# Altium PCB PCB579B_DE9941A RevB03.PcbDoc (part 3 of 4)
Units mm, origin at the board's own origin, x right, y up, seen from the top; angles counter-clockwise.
Board outline 85.8 x 54.18 mm, 6 copper layers (Top, L2C, L3C, L4C, L5C, Bottom), stack 1.627 mm thick; 536 components, 371 nets, 1413 pads, 798 vias.
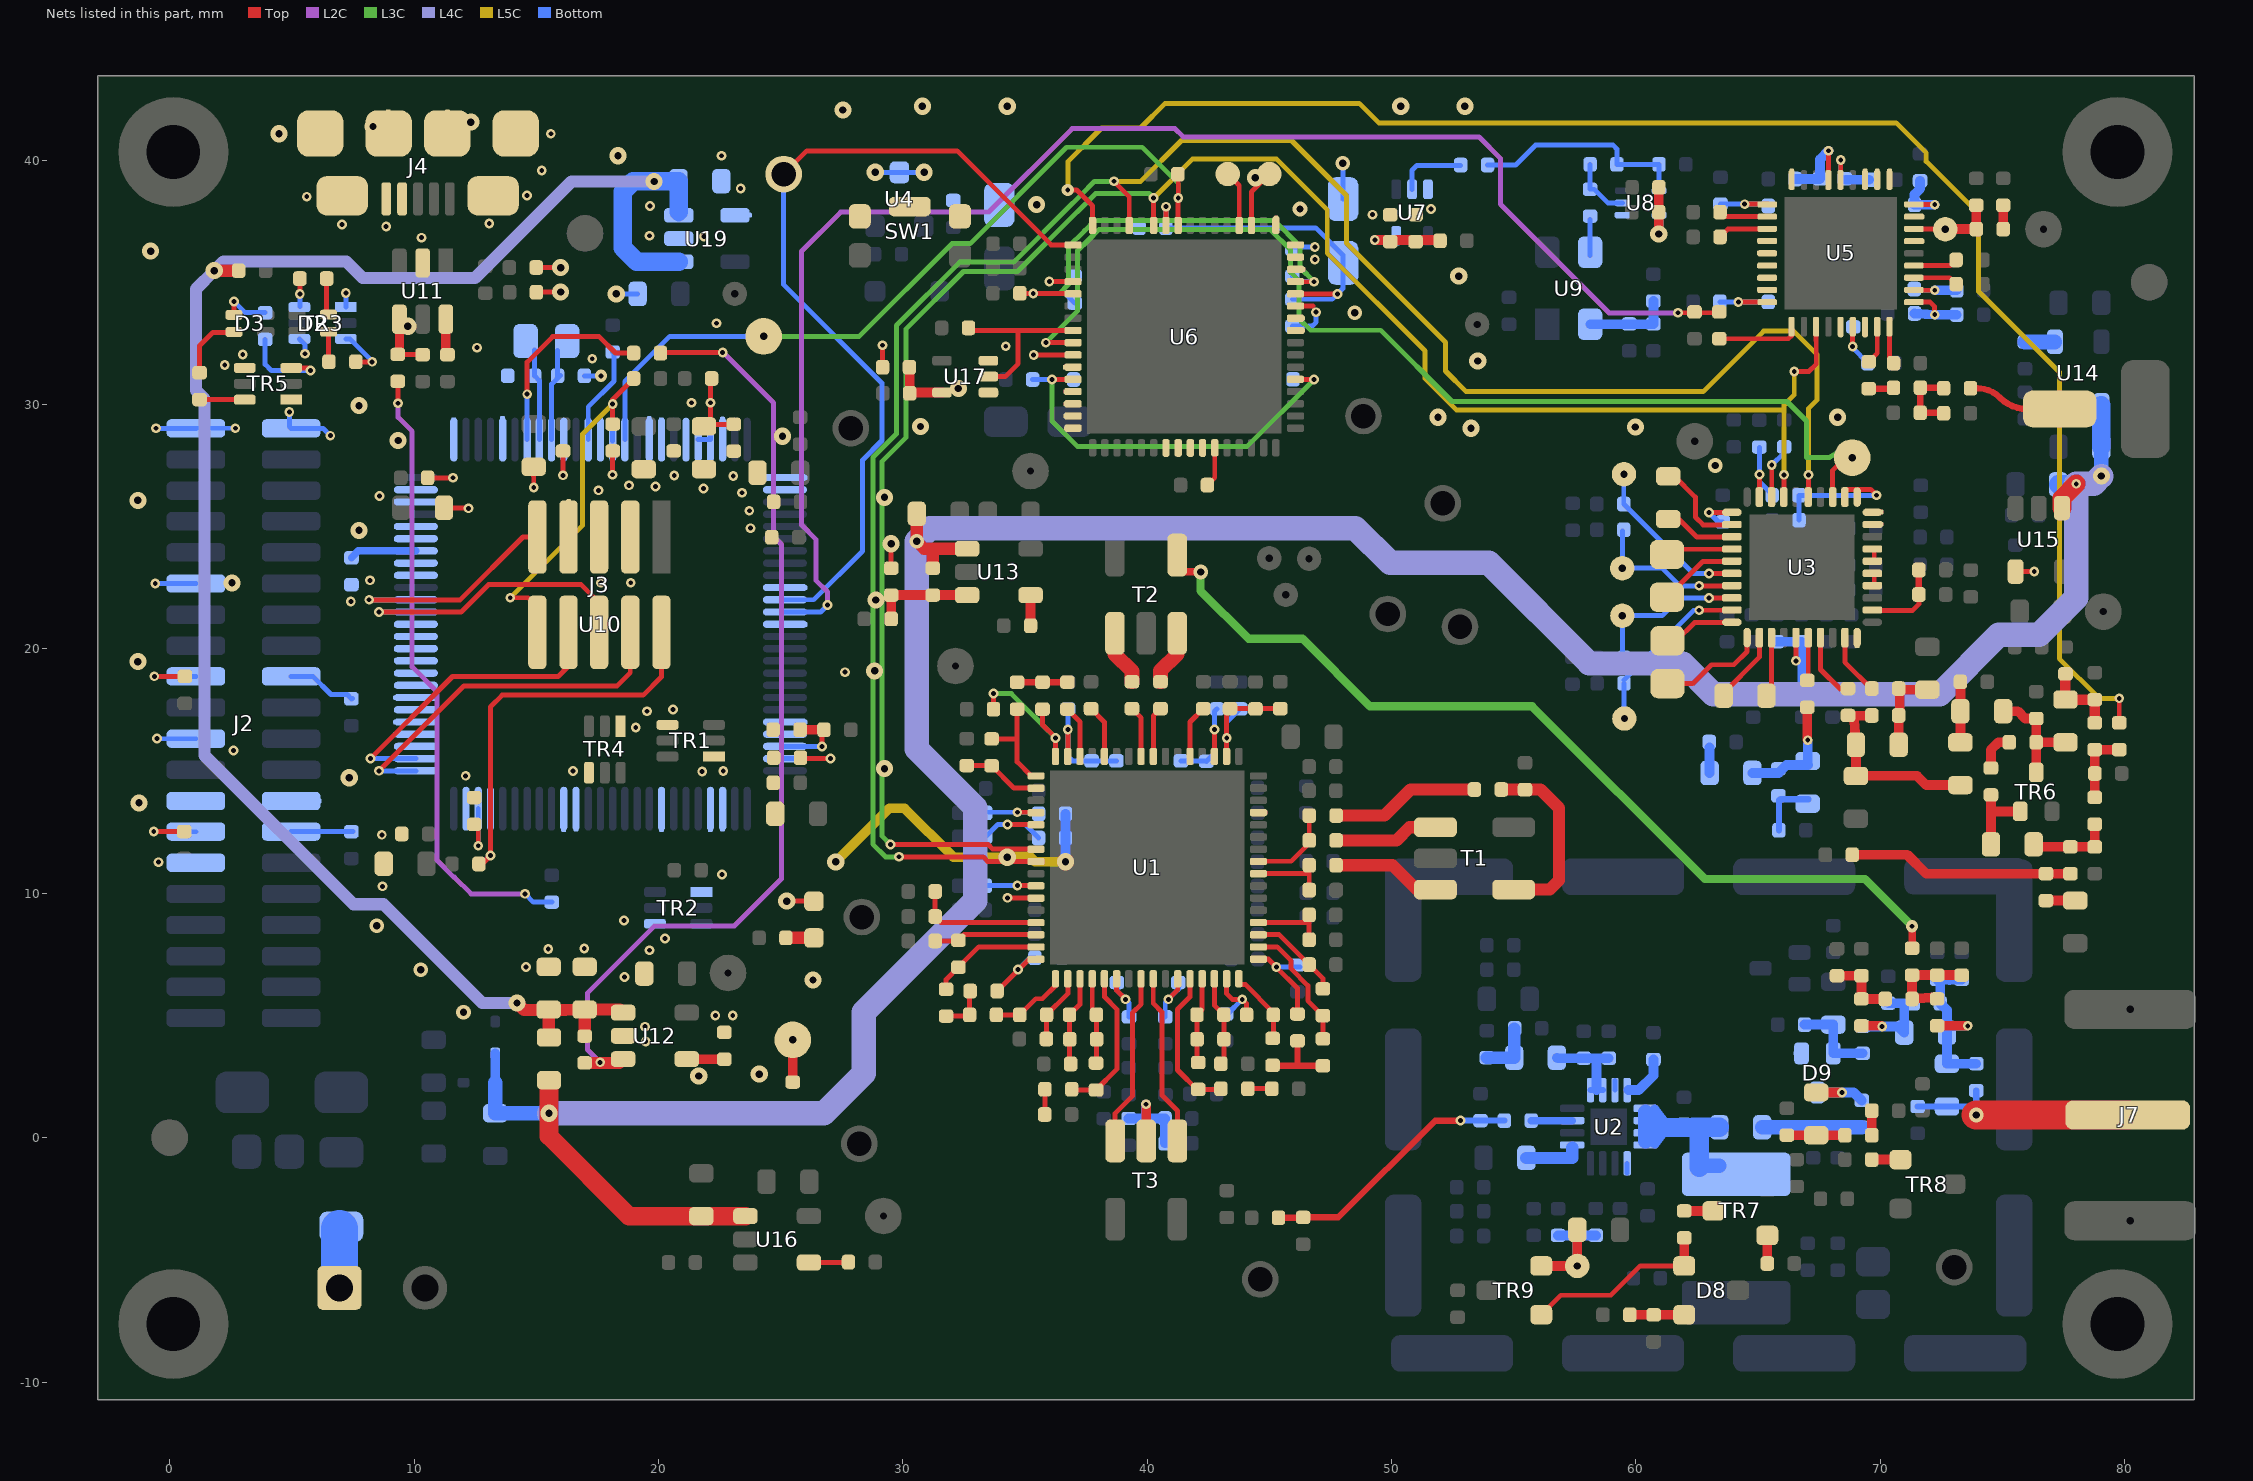
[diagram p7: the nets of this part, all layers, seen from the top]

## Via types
v1: diameter 0.4, hole 0.2, Top to Bottom, tented both sides, 372 vias
v2: diameter 0.7, hole 0.3, Top to Bottom, tented both sides, 177 vias
v3: diameter 0.7, hole 0.3, L5C to Bottom, tented both sides, 52 vias
v4: diameter 0.5, hole 0.2, Top to Bottom, tented both sides, 35 vias
v5: diameter 0.7, hole 0.3, Top to L2C, tented both sides, 33 vias
v6: diameter 0.6, hole 0.2, Top to Bottom, tented bottom, 30 vias
v7: diameter 0.6, hole 0.3, Top to L2C, tented bottom, 28 vias
v8: diameter 0.6, hole 0.3, Top to L2C, 24 vias
v9: diameter 0.6, hole 0.3, Top to Bottom, tented both sides, 22 vias
v10: diameter 0.6, hole 0.3, Top to Bottom, tented bottom, 9 vias
v11: diameter 0.5, hole 0.2, Top to Bottom, tented top, 6 vias
v12: diameter 0.45, hole 0.2, Top to Bottom, 5 vias
v13: diameter 0.6, hole 0.3, Top to Bottom, 3 vias
v14: diameter 0.406, hole 0.2, Top to Bottom, tented both sides, 2 vias

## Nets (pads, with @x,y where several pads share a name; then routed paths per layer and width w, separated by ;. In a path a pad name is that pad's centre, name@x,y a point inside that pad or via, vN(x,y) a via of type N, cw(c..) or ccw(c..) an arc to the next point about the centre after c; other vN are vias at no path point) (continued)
GNDD: C1.2 C2.2 C3.2 C4.2 C5.2 C6.2 C10.2 C12.2 C13.2 C19.1 C20.1 C21.1 C22.1 C23.1 C24.1 C25.1 C26.1 C27.1 C28.1 C29.1 C30.1 C31.1 C32.1 C33.1 C34.1 C35.2 C46.1 C47.1 C81.2 C82.2 C83.2 C84.2 C139.1 C144.1 C160.1 C192.2 C193.1 C194.1 C195.2 C196.2 C197.2 C198.1 C199.2 D4.2 J2.1 J2.2 J2.12 J2.22 J2.30 J3.3 J3.5 J4.5 J4.6 J4.7 J4.8 J4.11 R14.1 R20.1 R82.2 SW1.1 SW1.3 SW1.5 TP11.1 TR1.1 TR1.4 TR2.1 TR2.4 TR3.1 TR3.4 TR4.1 TR4.4 TR5.1 TR5.4 U1.59 U3.21 U3.22 U4.3 U6.4 U6.10 U6.43 U6.47 U6.48 U7.3 U10.10 U10.20 U10.27 U10.74 U10.99 U11.2 U12.2 U17.3 U19.2 | length 52.9
  Top w0.2: v1(34.288,9.812) U1.59@35.452,9.807
  Top w0.203: C193.1@10.554,26.997 v1@11.597,26.997 ; C194.1@11.229,25.772 v1@12.203,25.772 ; C29.1@14.896,27.448 v1(14.9,26.6) ; C34.1@15.002,35.605 15.007,35.6 v2(16,35.6) ; C35.2@15.01,34.589 15.021,34.6 v2(16,34.6) ; C24.1@16.096,28.098 16.096,27.104 v1(16.1,27.1) ; v1(18.125,27.125) 18.129,27.129 C25.1@18.129,28.097 ; v2(25.25,9.675) D4.2@26.363,9.674 ; C160.1@29.175,31.529 v1(29.175,32.425) ; C199.2@29.525,23.3 v5(29.525,24.3) ; v1(35.354,32.024) 35.358,32.028 U6.10@36.967,32.028 ; v1(35.996,35.028) U6.4@36.967,35.028 ; U6.43@46.067,34.028 46.787,34.028 ; U3.22@68.55,26.213 U3.22@68.55,26.525 ; U3.22@68.55,26.525 69.6,26.525 v1(69.848,26.284) ; U3.21@69.05,26.213 U3.21@69.05,26.525
  Top w0.4: R82.2@25.5,2.275 TP11.1@25.5,4
  L5C w0.4: v2(27.255,11.285) 29.445,13.475 30.075,13.475 32.075,11.475 v3(34.275,11.475) 34.3,11.5 35.201,11.5 35.413,11.288 v3(36.658,11.288)
  Bottom w0.2: C198.1@16.974,31.171 v4(17.652,31.171)
  Bottom w0.203: v1@-0.582,22.672 J2.12@1.076,22.672 ; v1@-0.556,29.022 J2.2@1.076,29.022 1.081,29.027 v1(2.69,29.027) ; v1@-0.505,16.322 J2.22@1.076,16.322 ; v1(4.9,29.688) 4.9,29.098 J2.1@4.976,29.022 6.276,29.022 v1(6.576,28.722) ; TR3.4@5.311,32.68 5.545,32.447 v1(5.545,32.075) ; TR3.1@7.211,33.98 v1(7.211,34.564) ; v2(18.275,34.525) C197.2@19.15,34.525 ; v2@28.878,39.497 U4.3@29.864,39.497 v2@30.872,39.497 ; C2.2@45.942,33.203 46.744,33.203 46.911,33.371 v1(46.911,33.777) ; C6.2@46.033,36.444 v1(46.861,36.444) ; v9(48.004,39.873) 48.004,38.425 C1.2@48.014,38.397 ; C139.1@66.673,25.268 C144.1@66.673,26.284 v1(69.848,26.284)
  Bottom w0.4: v3(36.658,11.288) C46.1@36.658,12.26 C47.1@36.658,13.251
  other v1: 19.479,3.932 19.454,4.542 22.33,4.995 23.041,4.995 18.616,6.574 14.577,6.98 19.632,7.666 15.492,7.717 16.965,7.742 20.267,8.148 18.59,8.885 8.71,10.282 22.604,10.765 -0.46,11.273 8.684,12.39 12.113,14.803 21.791,14.981 16.508,15.006 22.654,15.006 2.614,15.845 -0.51,16.327 19.073,16.784 19.53,17.445 20.597,17.521 27.633,19.045 7.414,21.941 -0.587,22.677 17.651,22.703 18.87,22.703 8.202,22.804 23.772,24.938 23.721,25.649 12.225,25.75 8.583,26.259 23.416,26.386 17.549,26.487 21.842,26.563 19.886,26.64 18.794,26.69 11.6,27 23.061,27.071 20.648,27.097 -0.561,29.027 21.359,30.069 2.258,31.618 17.295,31.872 2.995,32.05 12.575,32.325 34.211,32.38 22.375,33.325 46.861,35.936 10.31,36.825 21.867,36.876 19.632,36.901 8.862,37.282 7.059,37.358 13.079,37.409 49.223,37.765 51.61,37.993 19.657,38.12 5.611,38.501 14.628,38.552 23.366,38.832 15.225,39.575 22.578,40.178 15.6,41.075
  other v2: 24.125,2.6 26.325,6.45 -1.25,13.7 7.35,14.725 -1.3,19.475 -1.3,26.075 51.9,29.475 7.75,29.95 53.525,31.775 52.75,35.25 -0.775,36.275 28.875,39.5 30.875,39.5 18.35,40.175 4.475,41.075 27.55,42.05 30.8,42.2 34.275,42.2 50.375,42.2 53,42.2
  other v3: 21.65,2.525 29.25,15.1 28.85,19.1 28.9,22 2.55,22.7 7.75,24.85 29.25,26.2 9.35,28.525 25.075,28.7 53.25,29.025 59.975,29.075 30.725,29.1 68.25,29.475 32.275,30.65 9.75,33.2 35.475,38.175 44.425,39.275 8.325,41.375 12.325,41.55
  other v9: 12.025,5.125 10.275,6.875 8.475,8.675 63.25,27.5 48.5,33.75 46.25,38
GPIOA/LNA: R102.1 U6.64 | length 67.3
  Top w0.203: v4(36.751,38.781) 37.107,38.781 37.767,38.121 U6.64@37.767,37.328 ; R102.1@79.775,16.975 v1(79.775,17.975)
  L5C w0.203: v4(36.751,38.781) 36.751,39.937 38.13,41.315 39.724,41.315 40.733,42.324 48.676,42.324 49.475,41.525 70.65,41.525 71.875,40.3 71.875,39.95 74.025,37.8 74.025,34.625 77.325,31.325 77.325,19.6 78.95,17.975 v1(79.775,17.975)
GPIOB/SLOT: TL10.1 U6.1 U10.36 | length 35.2
  Top w0.2: TL10.1@25.125,39.425 26.075,40.375 32.225,40.375 36.072,36.528 U6.1@36.967,36.528
  Bottom w0.2: TL10.1@25.125,39.425 25.125,34.9 29.15,30.875 29.15,28.525 28.35,27.725 28.35,24 26.358,22.008 U10.36@25.179,22.008
GPIOC/TXD: R122.1 U6.8 U17.2 | length 7.1
  Top w0.203: R122.1@32.792,33.028 U6.8@37.067,33.028 ; U17.2@33.503,31.14 34.19,31.14 34.719,31.669 34.719,33.028
GPIOD/RXD: TP17.1 U3.23 U6.9 | length 45.7
  Top w0.203: v1@35.853,32.533 U6.9@37.062,32.533 ; U3.23@68.05,26.275 68.05,27.301 TP17.1@68.67,27.921
  L3C w0.203: v1(35.853,32.528) 37.158,33.833 37.158,36.292 37.597,36.731 37.601,36.731 38.021,37.151 45.038,37.151 45.87,36.319 45.87,35.404 46.206,35.068 46.206,33.519 46.689,33.036 49.557,33.036 52.474,30.119 66.181,30.119 66.975,29.325 66.975,27.836 67.111,27.825 67.9,27.825 68.211,28.011 68.806,28.011 TP17.1@68.857,27.96
IASIG: C54.1 U1.46 | length 2.2
  Top w0.2: C54.1@36.734,17.535 37.252,17.017 U1.46@37.252,15.507
IRQN: R4.1 TP2.1 U6.57 U10.15 | length 32.5
  Top w0.2: U6.57@41.267,37.228 v1@41.267,38.442 ; v1(41.272,38.442) R4.1@41.272,39.558
  L3C w0.2: TP2.1@24.305,32.786 28.215,32.786 32.012,36.583 32.759,36.583 36.7,40.524 39.794,40.524 41.272,39.047 v1(41.272,38.442)
  Bottom w0.2: U10.15@18.629,28.558 18.629,30.196
  Bottom w0.203: 18.629,30.196 18.629,30.946 20.47,32.786 TP2.1@24.305,32.786
JNTRST: J3.9 U10.90 | length 9.8
  Top w0.203: v1(8.166,22.008) 11.892,22.008 14.462,24.578 J3.9@15.049,24.578
  Bottom w0.203: v1(8.166,22.008) U10.90@10.029,22.008
JTCK: J3.4 U10.76 | length 15.1
  Top w0.203: v1(8.566,15.008) 12.046,18.488 18.311,18.488 18.849,19.027 J3.4@18.849,20.678
  Bottom w0.203: v1(8.566,15.008) U10.76@10.079,15.008
JTDI: J3.8 U10.77 | length 12.9
  Top w0.203: v1(8.216,15.508) 11.577,18.869 15.898,18.869 16.324,19.296 J3.8@16.324,20.678
  Bottom w0.203: v1(8.216,15.508) U10.77@10.079,15.508
JTDO: J3.6 U10.89 | length 12.5
  Top w0.203: v1(8.566,21.508) 11.931,21.508 13.051,22.628 16.837,22.628 17.574,21.892 J3.6@17.574,20.678
  Bottom w0.203: v1(8.566,21.508) U10.89@10.079,21.508
JTMS: J3.2 R15.2 U10.72 | length 17.9
  Top w0.203: R15.2@12.654,11.198 12.783,11.198 v1(13.129,11.545) 13.129,17.627 13.61,18.107 19.377,18.107 20.124,18.854 J3.2@20.124,20.678
  Bottom w0.203: v1(13.129,11.545) U10.72@13.129,13.458
LOCKDET: C102.1 R87.1 U10.37 | length 60.7
  Top w0.2: v1(61.72,33.752) 63.375,33.752 R87.1@63.412,33.788
  L2C w0.203: v1(26.923,21.792) 26.923,22.327 26.444,22.806 26.444,24.482 25.855,25.071 25.855,36.266 27.455,37.866 33.51,37.866 36.932,41.288 41.137,41.288 41.475,40.95 53.575,40.95 54.45,40.075 54.45,38.2 58.898,33.752 v1(61.72,33.752)
  Bottom w0.203: U10.37@25.179,21.508 26.64,21.508 v1(26.923,21.792)
MISO: U1.56 U3.25 U6.61 | length 84.7
  Top w0.203: v1(29.848,11.492) 33.286,11.492 33.471,11.307 U1.56@35.452,11.307 ; v1(38.637,39.132) 39.267,38.502 U6.61@39.267,37.328 ; U3.25@67.056,26.421 v1(67.056,27.121)
  L3C w0.203: v1(29.848,11.492) 29.293,11.492 28.777,12.008 28.777,27.831 29.743,28.796 29.743,33.238 32.327,35.823 34.538,35.823 36.967,38.251 36.971,38.251 37.281,38.562 37.281,38.565 37.848,39.132 v1(38.637,39.132)
  L5C w0.203: v1(38.637,39.132) 39.736,39.132 41.407,40.803 45.905,40.803 48.156,38.552 48.156,36.596 52.208,32.545 52.208,31.367 53.052,30.523 62.748,30.523 65.225,33 66.45,33 67.4,32.05 67.4,30.175 67.056,29.831 v1(67.056,27.121)
MOSI: U1.55 U3.27 U5.12 U6.59 | length 81.7
  Top w0.2: v1(40.262,38.446) 40.262,37.243 U6.59@40.272,37.233 ; U3.27@66.056,26.421 v1(66.056,27.121) ; v1(66.475,31.35) 67.075,31.35 67.375,31.65 67.375,31.95 U5.12@67.372,33.185
  Top w0.203: v1(29.498,11.992) 33.492,11.992 33.677,11.807 U1.55@35.452,11.807
  L3C w0.203: v1(29.498,11.992) 29.158,12.332 29.158,27.673 30.124,28.638 30.124,33.08 32.485,35.442 34.696,35.442 37.125,37.87 37.128,37.87 37.89,38.632 40.077,38.632 v1(40.262,38.446)
  L5C w0.2: v1(40.262,38.446) 41.862,40.046 45.286,40.046 47.369,37.968 47.369,36.19 51.372,32.186 51.372,31.053 52.659,29.766 66.047,29.766 66.047,29.966 66.056,29.975 ; v1(66.056,27.121) 66.056,29.975 ; v1(66.475,31.35) 66.475,30.394 66.056,29.975
NetC1_1: C1.1 C2.1 C3.1 U6.44 U6.58 | length 14.5
  Top w0.2: U6.58@40.772,37.392 v1(40.772,38.092) ; U6.44@46.132,34.522 v1(47.789,34.522)
  Bottom w0.2: C2.1@45.942,34.303 47.57,34.303 v1(47.789,34.522) 48.014,34.747 C1.1@48.014,35.797
  Bottom w0.203: v1@40.767,38.087 C3.1@40.767,37.228 46.895,37.228 48.014,36.109 C1.1@48.014,35.797
NetC5_1: C5.1 C6.1 R3.2 U6.5 U6.45 | length 20.8
  Top w0.2: R3.2@34.803,34.533 U6.5@36.903,34.533 ; U6.45@46.131,35.023 v1(46.831,35.023)
  L3C w0.203: v1(35.337,34.536) 36.403,34.536 36.777,34.91 36.777,36.449 37.439,37.112 37.443,37.112 37.863,37.532 45.195,37.532 46.251,36.476 46.251,35.603 v1(46.831,35.023)
  Bottom w0.203: v1@35.337,34.533 36.653,34.533 C5.1@37.039,34.147 ; C6.1@45.942,35.253 46.172,35.023 v1(46.831,35.023)
NetC7_1: C7.1 C8.1 R2.2 U6.12 U6.37 | length 18.1
  Top w0.2: v1(36.1,31.025) U6.12@36.967,31.028 ; U6.37@46.131,31.023 v1(46.831,31.023)
  L3C w0.2: v1(36.1,31.025) 36.1,29.325 37.153,28.272 44.081,28.272 v1(46.831,31.023)
  Bottom w0.2: C7.1@45.967,31.028 45.972,31.023 v1(46.831,31.023)
  Bottom w0.203: R2.2@35.314,31.022 v1(36.1,31.025) C8.1@36.989,31.022
NetC11_2: C11.2 U6.27 | length 1.8
  Top w0.2: C11.2@42.465,26.702 42.767,27.004 U6.27@42.767,28.328
NetC12_1: C12.1 C13.1 R7.2 U7.5 | length 3.3
  Top w0.4: v1(49.315,36.735) R7.2@51.947,36.735
  Bottom w0.4: v1(49.315,36.735) U7.5@50.021,36.735
NetC14_2: C14.2 R8.1 U8.5 | length 2.5
  Top w0.4: v2(60.932,36.977) R8.1@60.932,37.866 C14.2@60.932,38.875
  Bottom w0.4: v2(60.932,36.977) 60.932,37.587
NetC15_2: C15.2 C16.1 R9.1 U9.4 | length 3.5
  Bottom w0.4: U9.4@58.126,33.28 C15.2@60.7,33.28 ; C15.2@60.714,33.294 R9.1@60.714,34.234
NetC17_1: C17.1 U9.3 | length 1.5
  Bottom w0.2: U9.3@58.123,36.088 C17.1@58.123,37.562
NetC17_2: C17.2 R11.1 U8.2 | length 2.6
  Bottom w0.2: R11.1@58.123,39.822 C17.2@58.123,38.806 58.291,38.806 58.849,38.247 U8.2@59.446,38.247
NetC19_2: C19.2 R139.2 U10.48 | length 2.9
  Top w0.203: v1(26.693,16.008) R139.2@26.693,16.459
  Top w0.4: C19.2@25.797,16.691 R139.2@26.772,16.691
  Bottom w0.203: U10.48@25.179,16.008 v1(26.693,16.008)
NetC31_2: C31.2 C32.2 R18.2 U10.21 U10.22 | length 4.8
  Top w0.203: C31.2@21.953,29.189 C32.2@23.086,29.189 ; C31.2@22.129,29.366 v1(22.129,30.072) R18.2@22.129,31.015
  Bottom w0.203: U10.21@21.629,28.558 U10.22@22.129,28.558 v1(22.129,30.072)
NetC33_2: C33.2 U10.73 | length 2.2
  Top w0.203: v1(12.629,11.945) C33.2@12.629,12.655
  Bottom w0.203: v1(12.629,11.945) U10.73@12.629,13.458
NetC36_2: C36.2 R30.1 T1.6 | length 7.6
  Top w0.5: R30.1@54.491,14.244 C36.2@55.46,14.237 56.094,14.244 56.851,13.488 56.851,10.533 56.47,10.152 T1.6@54.996,10.152
NetC45_1: C45.1 R35.1 U1.24 | length 3.2
  Top w0.2: U1.24@44.452,10.807 46.632,10.807 ; C45.1@46.632,10.13 46.632,10.807 ; R35.1@46.632,11.146 46.632,10.807
NetC46_2: C46.2 R38.1 U1.53 | length 3.8
  Top w0.2: v1(34.288,12.812) U1.53@35.452,12.807
  Bottom w0.2: R38.1@33.391,12.314 33.889,12.812 v1(34.288,12.812) 35.005,12.812 C46.2@35.558,12.26
NetC47_2: C47.2 R39.1 U1.52 | length 2.8
  Top w0.2: v1(34.688,13.312) U1.52@35.388,13.312
  Bottom w0.2: R39.1@33.414,13.312 v1(34.688,13.312) C47.2@35.496,13.312
NetC48_2: C48.2 R45.2 U1.64 | length 3
  Top w0.2: R45.2@33.857,5.998 35.166,7.307 U1.64@35.452,7.307
  Bottom w0.2: v1(34.719,6.878) 35.199,7.358 C48.2@35.405,7.358
NetC50_1: C50.1 R48.2 U1.1 | length 3.2
  Top w0.2: C50.1@33.832,5.023 R48.2@34.782,5.023 35.444,5.685 35.71,5.685 36.252,6.226 U1.1@36.252,6.507
NetC50_2: C50.2 R44.1 R45.1 | length 2
  Top w0.2: R44.1@31.773,4.973 32.682,4.973 C50.2@32.732,5.023 32.732,5.973 R45.1@32.757,5.998
NetC51_2: C51.2 R48.1 U1.2 | length 2.8
  Top w0.2: C51.2@35.873,4.035 R48.1@35.873,5.014
  Top w0.203: R48.1@35.882,5.023 36.752,5.893 U1.2@36.752,6.507
NetC52_1: C52.1 R51.1 R54.2 U1.4 | length 3.4
  Top w0.203: C52.1@37.752,5.197 U1.4@37.752,6.507 ; C52.1@37.844,4.85 C52.1@37.923,4.929 ; R54.2@37.923,3.064 C52.1@37.923,4.929 ; C52.1@37.923,5.026 C52.1@37.923,4.929
NetC52_2: C52.2 R49.2 R51.2 U1.3 | length 3.6
  Top w0.2: R49.2@36.823,3.108 C52.2@36.823,5.026 37.252,5.455 U1.3@37.252,6.507
NetC53_1: C53.1 R53.1 U1.49 | length 4.2
  Top w0.2: C53.1@33.636,16.316 34.575,16.316 ; R53.1@34.677,17.535 34.677,15.376 35.246,14.807 U1.49@35.552,14.807
NetC53_2: C53.2 R50.1 U1.50 | length 3.3
  Top w0.2: R50.1@32.62,15.223 C53.2@33.628,15.223 ; C53.2@33.636,15.216 34.544,14.307 U1.50@35.552,14.307
NetC54_2: C54.2 C56.2 R53.2 | length 2.1
  Top w0.254: R53.2@34.677,18.635 C56.2@35.718,18.635 C54.2@36.734,18.635
NetC55_1: C55.1 R55.2 | length 1
  Top w0.203: R55.2@35.814,0.955 C55.1@35.814,1.978
NetC55_2: C55.2 R54.1 U1.5 | length 6.1
  Top w0.203: C55.2@36.944,1.948 R54.1@37.907,1.948 38.76,2.801 38.76,5.251 38.252,5.759 U1.5@38.252,6.507
NetC56_1: C56.1 R57.1 U1.48 | length 6.2
  Top w0.2: R57.1@33.712,17.538 v1(33.712,18.17) ; C56.1@35.718,17.535 35.718,16.89 v1(36.254,16.355)
  Top w0.203: U1.48@36.254,15.509 v1(36.254,16.355)
  L3C w0.203: v1(33.712,18.17) 34.439,18.17 v1(36.254,16.355)
NetC57_1: C57.1 R52.2 U1.6 | length 2.6
  Top w0.2: U1.6@38.752,6.507 38.752,6.021 v1(39.114,5.659)
  Bottom w0.2: C57.1@38.761,6.347 38.761,6.012 v1(39.114,5.659) 39.257,5.516 R52.2@39.257,4.94
NetC59_1: C59.1 T2.1 | length 2.3
  Top w0.6: C59.1@40.544,18.655 40.544,19.1 41.23,19.786 T2.1@41.23,20.636
NetC59_2: C59.2 U1.40 | length 2.2
  Top w0.2: U1.40@40.252,15.507 40.252,17.262 C59.2@40.544,17.555
NetC60_1: C60.1 R58.2 | length 0.9
  Top w0.2: C60.1@44.153,2.003 R58.2@45.099,2.003
NetC60_2: C60.2 R60.1 U1.12 | length 6.1
  Top w0.2: R60.1@42.091,1.973 C60.2@43.024,1.973
  Top w0.203: 41.244,2.768 R60.1@42.096,1.916 ; 41.244,2.801 41.244,5.251 41.752,5.759 U1.12@41.752,6.507
NetC61_1: C61.1 T2.3 | length 2.3
  Top w0.6: T2.3@38.68,20.636 38.68,19.785 39.38,19.085 39.38,18.659 C61.1@39.376,18.655
NetC61_2: C61.2 U1.41 | length 2.2
  Top w0.2: C61.2@39.376,17.555 39.752,17.179 U1.41@39.752,15.507
NetC62_1: C62.1 R62.1 R65.2 U1.14 | length 3.6
  Top w0.2: U1.14@42.752,6.607 42.752,5.411 C62.1@43.137,5.026 R65.2@43.137,3.144
NetC62_2: C62.2 R60.2 R62.2 U1.13 | length 3.5
  Top w0.203: R60.2@42.037,3.127 C62.2@42.037,4.972 ; C62.2@42.081,4.929 C62.2@42.037,4.972 ; U1.13@42.252,6.507 42.252,5.24 C62.2@42.037,5.026 C62.2@42.037,4.972
NetC63_1: C63.1 R59.2 U1.11 | length 2.6
  Top w0.2: v1(40.866,5.659) 41.252,6.045 U1.11@41.252,6.507
  Bottom w0.2: R59.2@40.741,4.94 40.741,5.534 v1(40.866,5.659) 41.275,6.068 C63.1@41.275,6.347
NetC65_2: C65.2 C67.2 R63.1 U1.47 | length 5.1
  Top w0.203: U1.47@36.754,15.605 v1(36.754,16.705)
  Bottom w0.2: C65.2@37.724,15.417 C67.2@38.74,15.417
  Bottom w0.203: R63.1@36.754,17.521 v1(36.754,16.705) 36.754,15.611 36.947,15.417 C65.2@37.724,15.417
NetC66_2: C66.2 C68.2 R64.1 U1.35 | length 4.5
  Top w0.203: U1.35@42.754,15.605 v1(42.754,16.705)
  Bottom w0.203: C68.2@41.382,15.417 C66.2@42.445,15.417 ; C66.2@42.421,15.394 C66.2@42.445,15.417 ; R64.1@42.855,17.543 42.754,17.442 v1(42.754,16.705) 42.754,15.726 C66.2@42.445,15.417
NetC69_2: C69.2 R66.1 U1.15 | length 3.1
  Top w0.2: U1.15@43.252,6.507 43.252,5.89 43.482,5.659 v1(43.889,5.659) 44.066,5.482 R66.1@44.066,5.023 R66.1@43.94,5.15
  Bottom w0.2: C69.2@43.228,5.057 43.287,5.057 v1(43.889,5.659)
NetC70_1: C70.1 R66.2 U1.16 | length 3.1
  Top w0.2: U1.16@43.752,6.507 43.752,6.304 43.787,6.269 44.016,6.269 45.166,5.118 R66.2@45.166,5.023 C70.1@45.166,4.092
  Top w0.203: R66.2@45.169,5.026 R66.2@45.183,5.026
NetC70_2: C70.2 R67.1 R68.1 | length 3
  Top w0.254: C70.2@45.151,2.941 R68.1@47.191,2.941 ; 46.149,2.963 R67.1@46.149,3.957
NetC71_2: C71.2 R67.2 U1.17 | length 4.5
  Top w0.2: U1.17@44.454,7.309 44.957,7.309 v1(45.286,6.98) ; v1(45.286,6.98) 46.149,6.116 R67.2@46.149,5.057 R67.2@45.972,5.235
  Bottom w0.2: v1(45.286,6.98) C71.2@46.251,6.98
NetC72_2: C72.2 C73.2 R75.1 R76.2 U1.34 | length 5.5
  Top w0.2: U1.34@43.252,15.507 43.252,17.417 C73.2@43.389,17.555 45.393,17.555 C72.2@45.405,17.543
  Bottom w0.2: v1(43.254,16.355) 43.254,16.992 R75.1@43.805,17.543
NetC79_2: C79.2 C80.2 R78.1 T3.2 | length 4.6
  Top w0.4: T3.2@39.965,-0.135 v1@39.965,1.356
  Bottom w0.4: R78.1@39.241,0.782 C79.2@40.731,0.782 C80.2@40.731,-0.234 ; 39.953,0.808 v1(39.953,1.367)
NetC82_1: C82.1 C83.1 C196.1 L2.1 R80.1 R142.2 U12.1 U19.1 U19.3 | length 73.6
  Top w0.5: v2(1.825,35.475) R80.1@2.825,35.475 ; v2(14.215,5.51) 14.5,5.225 15.509,5.216 L2.1@15.509,4.116 ; C82.1@15.51,5.216 C83.1@16.983,5.241 ; R142.2@16.983,4.157 C83.1@16.983,5.241 ; U12.1@18.43,5.241 C83.1@16.983,5.241
  L4C w0.5: v2(14.215,5.51) 12.79,5.51 8.75,9.55 7.521,9.55 1.43,15.641 1.43,30.22 1.075,30.575 1.075,34.725 v2(1.825,35.475) 2.2,35.85 7.225,35.85 7.9,35.175 12.5,35.175 16.45,39.125 v2(19.825,39.125)
  Bottom w0.5: U19.3@20.836,37.738 U19.3@20.836,37.881
  Bottom w0.75: C196.1@20.826,39.136 20.836,39.126 U19.3@20.836,37.881
  Bottom w0.762: C196.1@20.826,39.136 18.971,39.136 18.54,38.705 18.54,36.419 19.12,35.838 U19.1@20.836,35.838
NetC84_1: C84.1 U12.4 | length 1.5
  Top w0.381: U12.4@21.157,3.214 U12.4@21.162,3.214 ; U12.4@21.162,3.209 C84.1@22.698,3.209
NetC85_1: C85.1 C89.1 C91.1 C95.1 C98.1 D5.1 D6.1 L2.2 R143.2 U13.1 U14.1 U15.1 U16.1 | length 121.4
  Top w0.5: C85.1@30.575,25.525 v9(30.575,24.4) 30.877,24.098 31.225,24.098 ; R143.2@31.225,23.3 31.225,24.098 ; U13.1@32.631,24.098 31.225,24.098
  Top w0.762: L2.2@15.525,2.35 v2(15.525,1) 15.525,0.063 18.799,-3.21 C98.1@21.758,-3.21 U16.1@23.561,-3.21 ; U15.1@77.433,25.762 77.433,26.168 v1(78.017,26.753)
  L4C w1: v2(15.525,1) 26.775,1 28.4,2.625 28.4,5.125 32.967,9.692 32.967,13.508 30.572,15.902 30.572,24.397 v9(30.575,24.4) 31.113,24.938 48.522,24.938 49.944,23.515 53.983,23.515 58.097,19.401 61.917,19.401 63.167,18.15 72.432,18.15 74.851,20.569 76.494,20.569 78.017,22.092 v1(78.017,26.753) 78.724,26.753 v2(79.042,27.071)
  Bottom w0.4: D6.1@13.325,2.25 D5.1@13.325,3.45
  Bottom w0.6: D6.1@13.325,2.25 C89.1@13.325,1 v2(15.525,1) ; v2(79.042,27.071) C91.1@79.042,28.265
  Bottom w0.762: C95.1@77.28,26.727 v1@77.992,26.727 ; C91.1@79.042,28.265 U14.1@79.042,29.967
NetC87_1: C87.1 U13.4 | length 1.2
  Top w0.4: C87.1@35.231,20.953 U13.4@35.231,22.198
NetC93_1: C93.1 U14.4 | length 1.2
  Bottom w0.6: C93.1@75.918,32.558 U14.4@77.133,32.558
NetC96_1: C96.1 U15.4 | length 1.5
  Top w0.2: U15.4@75.535,23.16 v1(76.299,23.16)
  Bottom w0.2: C96.1@75.542,23.16 v1(76.299,23.16)
NetC99_1: C99.1 U16.4 | length 1.6
  Top w0.2: U16.4@26.161,-5.11 C99.1@27.757,-5.11
NetC100_1: C100.1 C101.1 TP14.1 U5.25 | length 4
  Top w0.203: U5.25@71.322,37.185 U5.25@71.372,37.185 TP14.1@73.08,37.185
  Top w0.4: TP14.1@72.668,37.175 C100.1@73.925,37.175 C101.1@73.925,38.15
NetC100_2: C100.2 R85.1 | length 1
  Top w0.4: C100.2@75.025,37.175 R85.1@75.025,38.15
NetC103_1: C103.1 R86.2 U5.32 | length 2.3
  Top w0.2: U5.32@68.377,39.299 v1(68.377,39.999)
  Bottom w0.2: C103.1@68.377,39.401 v1(68.377,39.999)
  Bottom w0.4: C103.1@68.582,39.197 R86.2@69.539,39.197
NetC104_1: C104.1 R88.1 U5.15 | length 2.4
  Top w0.2: v1(68.867,32.371) U5.15@68.867,33.071
  Bottom w0.2: C104.1@68.867,33.15 v1(68.867,32.371) 68.867,32.319 R88.1@69.492,31.694
NetC105_1: C105.1 R89.2 U5.33 | length 3.4
  Top w0.203: U5.33@67.878,39.281 v1(67.878,40.381)
  Bottom w0.203: C105.1@67.516,39.222 C105.1@67.528,39.235
  Bottom w0.4: R89.2@66.514,39.222 C105.1@67.516,39.222 ; C105.1@67.528,39.235 67.528,40.032 v1(67.878,40.381)
NetC106_1: C106.1 R90.2 U5.1 | length 2.8
  Top w0.2: v1(64.447,38.197) U5.1@65.41,38.197
  Bottom w0.2: R90.2@63.457,38.197 v1(64.447,38.197) C106.1@65.339,38.197
NetC107_1: C107.1 R91.2 U5.9 | length 3.2
  Top w0.2: v1(64.189,34.197) U5.9@65.41,34.197
  Bottom w0.2: R91.2@63.443,34.197 v1(64.189,34.197) C107.1@65.414,34.197
NetC108_1: C108.1 R92.2 U5.20 | length 2.4
  Top w0.2: U5.20@71.486,34.68 v1(72.225,34.675)
  Bottom w0.2: C108.1@71.432,34.68 v1(72.225,34.675)
  Bottom w0.4: v1(72.225,34.675) R92.2@73.125,34.675
NetC109_1: C109.1 R93.2 U5.27 | length 2.6
  Top w0.2: U5.27@71.486,38.18 v1(72.225,38.175)
  Bottom w0.4: R93.2@71.625,39.15 71.625,38.825 71.4,38.6 C109.1@71.4,38.175 v1(72.225,38.175)
NetC110_1: C110.1 R96.1 | length 1
  Top w0.259: C110.1@69.524,30.649 R96.1@70.5,30.649
NetC110_2: C110.2 U5.17 | length 1.6
  Top w0.2: C110.2@69.524,31.749 69.872,32.098 U5.17@69.872,33.235
NetC111_1: C111.1 U5.22 | length 1.9
  Top w0.203: U5.22@71.322,35.685 72.872,35.685 C111.1@73.1,35.914
NetC112_1: C112.1 U5.21 | length 1.9
  Top w0.203: U5.21@71.322,35.185 72.839,35.185 C112.1@73.1,34.923
NetC113_1: C113.1 U5.2 | length 2.1
  Top w0.2: C113.1@63.44,37.871 63.626,37.685 U5.2@65.422,37.685
NetC114_1: C114.1 U5.3 | length 2.1
  Top w0.2: C114.1@63.44,36.855 63.77,37.185 U5.3@65.422,37.185
NetC116_2: C116.2 L4.1 R101.1 R103.2 | length 3.2
  Top w0.43: R101.1@77.575,18.975 L4.1@77.575,17.925 C116.2@78.775,17.925 R103.2@78.775,16.975
NetC117_2: C117.2 R102.2 R103.1 R104.2 | length 2.9
  Top w0.4: R104.2@78.775,13.925 C117.2@78.775,14.9 R103.1@78.775,15.875 R102.2@79.775,15.875
NetC118_1: C118.1 C200.2 L4.2 L23.1 TR6.3 | length 4.9
  Top w0.4: L23.1@75.025,17.45 75.625,17.45 75.925,17.15 C200.2@76.375,17.15 C118.1@76.375,16.175 ; TR6.3@76.375,14.95 C118.1@76.375,16.175 ; L4.2@77.575,16.175 C118.1@76.375,16.175
NetC118_2: C118.2 R114.2 | length 1.6
  Top w0.4: R114.2@74.525,15.125 74.525,15.875 74.825,16.175 C118.2@75.275,16.175
NetC119_1: C119.1 C120.2 C121.2 | length 9.2
  Top w0.4: C119.1@68.85,11.575 71.1,11.575 71.875,10.8 C121.2@76.775,10.8 C120.2@77.775,10.8
NetC120_1: C120.1 C123.2 L6.1 R104.1 | length 3.5
  Top w0.4: L6.1@76.275,12 76.375,11.9 C120.1@77.775,11.9 C123.2@78.775,11.9 R104.1@78.775,12.825
NetC121_1: C121.1 L7.1 | length 1.2
  Top w0.4: C121.1@76.775,9.7 L7.1@77.975,9.7
NetC122_2: C122.2 L5.1 L23.2 | length 2.5
  Top w0.4: L5.1@73.275,16.175 L23.2@73.275,17.45 C122.2@73.275,18.65
NetC124_1: C124.1 C126.2 L8.2 L10.1 | length 3.4
  Top w0.4: L8.2@70.75,16.075 C124.1@70.75,17.275 ; C126.2@70.776,18.33 L10.1@71.925,18.33 ; C124.1@70.795,17.267 C126.2@70.795,18.311
NetC124_2: C124.2 C125.2 L5.2 L8.1 L9.2 | length 7.9
  Top w0.4: C125.2@68.725,17.262 68.933,17.054 L8.1@69,16.075 L9.2@69,14.8 69.003,14.803 71.497,14.803 71.875,14.425 L5.2@73.275,14.425 ; C125.2@68.73,17.267 C124.2@69.695,17.267
NetC125_1: C125.1 U3.7 | length 2.7
  Top w0.203: U3.7@67.55,20.375 67.55,19.158 68.346,18.362 C125.1@68.725,18.362
NetC126_1: C126.1 U3.9 | length 2.5
  Top w0.203: U3.9@68.55,20.375 68.55,19.456 C126.1@69.676,18.33
NetC127_1: C127.1 U3.1 | length 4.3
  Top w0.203: C127.1@61.295,18.578 62.32,18.578 63.091,19.35 64.006,19.35 64.55,19.894 U3.1@64.55,20.375
NetC127_2: C127.2 U3.40 | length 2.5
  Top w0.2: C127.2@61.65,20.328 62.397,21.075 U3.40@63.85,21.075
NetC128_1: C128.1 U3.34 | length 2
  Top w0.2: C128.1@61.838,24.075 U3.34@63.85,24.075
NetC128_2: C128.2 U3.35 | length 3.2
  Top w0.2: C128.2@61.269,22.111 62.733,23.575 U3.35@63.85,23.575
NetC129_1: C129.1 U3.3 | length 2.4
  Top w0.203: C129.1@65.339,18.085 65.55,18.296 U3.3@65.55,20.375
NetC129_2: C129.2 U3.2 | length 2.9
  Top w0.203: C129.2@63.589,18.085 63.589,18.197 65.05,19.658 U3.2@65.05,20.375
NetC130_1: C130.1 U3.32 | length 3.8
  Top w0.2: C130.1@61.32,27.062 61.579,27.062 62.431,26.21 62.431,25.395 62.751,25.075 U3.32@63.85,25.075
NetC130_2: C130.2 U3.33 | length 2.8
  Top w0.2: C130.2@61.32,25.312 61.752,25.312 62.489,24.575 U3.33@63.85,24.575
NetC131_2: C131.2 C132.2 R106.1 U3.5 | length 4
  Top w0.203: v1(66.545,19.511) U3.5@66.545,20.211
  Bottom w0.203: v1(66.545,19.511) 66.791,19.511 66.8,19.502
  Bottom w0.4: C132.2@65.758,20.29 C131.2@66.774,20.29 66.8,20.264 66.8,19.502 R106.1@66.8,18.308
NetC133_1: C133.1 C134.1 L11.1 | length 2.5
  Bottom w0.256: C134.1@65.85,12.575 65.85,13.8 65.91,13.847 L11.1@67.06,13.847
NetC133_2: C133.2 C135.2 L11.2 L12.1 | length 4.8
  Top w0.4: C135.2@67.009,17.611 67.009,16.283 v1(67.028,16.263)
  Bottom w0.4: L12.1@64.764,14.922 65.839,14.922 66.164,15.247 L11.2@67.039,15.247 ; L11.2@67.028,15.258 v1(67.028,16.263)
NetC135_1: C135.1 U3.6 | length 1.6
  Top w0.203: C135.1@67.05,18.752 U3.6@67.05,20.375
NetC137_2: C137.2 L12.2 | length 1.1
  Bottom w0.4: L12.2@63.006,14.916 C137.2@63.006,15.966
NetC144_2: C144.2 R116.2 U3.29 | length 2.9
  Top w0.203: U3.29@65.055,26.439 v1(65.055,27.139)
  Bottom w0.203: R116.2@65.055,28.249 v1(65.055,27.139) 65.055,26.84 C144.2@65.587,26.308
NetC152_2: C152.2 L13.2 R127.1 | length 2.4
  Top w0.4: C152.2@66.175,0.1 L13.2@67.375,0.1 R127.1@68.55,0.1
NetC154_2: C154.2 D8.2 R129.2 | length 2.2
  Top w0.4: R129.2@59.75,-7.25 C154.2@60.725,-7.25 D8.2@61.975,-7.25
NetC155_2: C155.2 R130.1 R131.1 TP23.1 TR9.2 | length 5.8
  Top w0.4: TR9.2@56.125,-5.25 TP23.1@57.6,-5.25 C155.2@57.6,-3.775
  Bottom w0.4: R131.1@56.814,-4.003 57.6,-4 ; TP23.1@57.6,-5.25 57.6,-4 ; R130.1@58.364,-4.003 58.35,-4.003 57.6,-4
NetC157_1: C157.1 C159.2 C167.1 L14.2 R134.2 | length 4
  Top w0.4: C167.1@72.325,5.75 L14.2@71.3,5.675 C157.1@71.3,6.65 R134.2@72.325,6.65 C159.2@73.3,6.65
NetC158_2: C158.2 C166.2 L14.1 R132.2 | length 2.9
  Top w0.4: R132.2@68.225,6.625 C158.2@69.225,6.625 C166.2@69.225,5.675 L14.1@70.2,5.675
NetC160_2: C160.2 R133.2 U17.5 | length 2.3
  Top w0.4: R133.2@30.284,30.455 C160.2@30.284,31.513 ; R133.2@30.318,30.49 U17.5@31.603,30.49
NetC166_1: C166.1 C172.1 C173.2 C176.2 L17.1 | length 4.5
  Top w0.4: C166.1@69.225,4.575 70.05,4.575 v1(70.075,4.55)
  Bottom w0.4: C173.2@69.275,4.55 v1(70.075,4.55) 70.725,4.55 L17.1@70.975,4.3 70.975,5.5 C176.2@70.325,5.5
NetC167_2: C167.2 C171.1 C172.2 C177.2 C178.2 L17.2 L18.1 | length 8
  Top w0.4: C167.2@72.325,4.575 v1(73.575,4.575)
  Bottom w0.4: C178.2@73.325,6.475 72.825,6.45 C177.2@72.325,6.475 72.45,6.35 C172.2@72.45,5.5 72.725,5.225 L17.2@72.725,4.675 ; v1(73.575,4.575) 72.7,4.575 L17.2@72.725,4.675 ; C171.1@73.925,3.025 L18.1@72.725,3.025 L17.2@72.725,4.3 L17.2@72.725,4.675
NetC171_2: C171.2 C179.2 J7.1 L18.2 | length 9.7
  Top w1.2: v13(73.925,0.925) J7.1@80.125,0.925
  Bottom w0.256: C179.2@71.525,1.275 L18.2@72.725,1.275 73.575,1.275 v13(73.925,0.925) C171.2@73.925,1.925
NetC173_1: C173.1 C191.1 D9.2 L22.1 | length 3.5
  Bottom w0.4: C191.1@66.9,4.625 L22.1@68.075,4.625 D9.2@68.075,3.45 C173.1@69.275,3.45
NetC174_1: C174.1 C181.2 C182.2 L19.2 | length 4.4
  Bottom w0.4: C181.2@67.25,0.275 C181.2@67.25,0.422 ; C182.2@68.25,0.275 C182.2@68.25,0.422
  Bottom w0.6: L19.2@65.164,0.422 67.25,0.422 67.25,0.425 68.25,0.425 68.25,0.422 C174.1@69.239,0.422
NetC174_2: C174.2 D9.3 L13.1 | length 3
  Top w0.4: L13.1@67.375,1.85 v1@68.424,1.85
  Bottom w0.4: D9.3@67.425,1.85 v1@68.424,1.85 ; v1(68.425,1.849) 68.912,1.849 C174.2@69.239,1.522
NetC175_1: C175.1 R135.2 R137.2 R138.2 | length 11
  Top w0.259: R135.2@45.374,-3.277 R137.2@46.401,-3.277 ; R137.2@46.38,-3.264 47.82,-3.264 51.781,0.697 v1(52.821,0.697)
  Bottom w0.256: v1(52.821,0.697) R138.2@53.639,0.697 ; R138.2@53.514,0.697 C175.1@54.614,0.697
NetC175_2: C175.2 U2.3 | length 1.7
  Bottom w0.3: C175.2@55.714,0.697 U2.3@57.389,0.697
NetC180_2: C180.2 L16.2 L19.1 U2.9 U2.10 U2.11 U2.12 | length 11
  Bottom w0.3: U2.12@60.389,-0.303 U2.12@60.389,-0.153 ; 60.389,1.047 U2.9@60.389,1.197
  Bottom w0.4: U2.12@60.764,-0.253 60.764,1.147 61.289,0.447 U2.12@60.764,-0.253
  Bottom w0.55: 62.339,0.322 62.339,0.422
  Bottom w0.6: U2.12@60.389,-0.153 U2.11@60.389,0.197 60.389,0.422 ; 60.389,1.047 U2.10@60.389,0.697 60.389,0.422 ; 60.589,0.422 60.389,0.422 ; L16.2@62.589,-1.203 62.914,-1.153 L16.2@63.414,-1.153
  Bottom w0.8: 60.589,0.422 62.589,0.397 ; 62.339,0.422 L19.1@63.414,0.422 ; L16.2@62.589,-1.203 62.589,0.397 ; L19.1@63.089,0.422 62.589,0.397
NetC183_2: C183.2 U2.8 | length 2
  Bottom w0.3: U2.8@59.639,1.947 U2.8@59.689,1.947
  Bottom w0.4: U2.8@59.689,1.947 60.114,1.947 60.714,2.547 C183.2@60.714,3.197
NetC187_2: C187.2 L20.2 L21.1 | length 2.3
  Bottom w0.508: L20.2@53.9,3.275 L21.1@55.014,3.272 C187.2@55.014,4.447
NetC188_2: C188.2 C189.2 L21.2 U2.5 U2.6 | length 3.9
  Bottom w0.254: U2.5@58.139,1.947 58.389,1.947 U2.6@58.639,1.947
  Bottom w0.4: L21.2@56.764,3.272 56.8,3.25 C189.2@57.862,3.249 C188.2@58.887,3.249 ; 58.389,1.947 58.389,3.247
NetC192_1: C192.1 U10.49 | length 3.1
  Top w0.203: C192.1@25.855,15.508 v1(27.043,15.508)
  Bottom w0.203: U10.49@25.179,15.508 v1(27.043,15.508)
NetC195_1: C195.1 U10.8 X1.2 | length 3.7
  Bottom w0.203: X1.2@14.934,32.226 C195.1@14.934,31.171 15.129,30.976 U10.8@15.129,28.558
NetC198_2: C198.2 U10.9 X1.1 | length 3.8
  Bottom w0.203: U10.9@15.629,28.558 15.629,30.828 C198.2@15.986,31.184 ; C198.2@15.874,31.171 X1.1@15.874,32.2
NetC199_1: C199.1 R143.1 R145.2 U13.3 | length 4.1
  Top w0.4: R145.2@29.525,21.225 C199.1@29.525,22.2 R143.1@31.225,22.2 32.628,22.2 U13.3@32.631,22.198
NetD2_3: D2.3 R21.2 | length 1.5
  Top w0.203: R21.2@6.429,35.152 6.429,33.751 D2.3@6.505,33.675
NetD2_4: D2.4 R22.2 | length 1.2
  Top w0.2: R22.2@6.505,31.758 D2.4@6.505,32.975
NetD3_3: D3.3 R27.2 | length 2.7
  Top w0.203: R27.2@1.225,31.3 1.225,32.4 1.775,32.95 2.5,32.95 D3.3@2.635,32.964
NetD3_4: D3.4 R26.2 | length 2
  Top w0.203: D3.4@2.639,33.669 v1(2.639,34.209)
  Bottom w0.203: v1(2.639,34.209) 3.089,33.759 R26.2@3.909,33.759
NetD4_1: D4.1 R79.2 | length 1.1
  Top w0.508: R79.2@25.22,8.174 D4.1@26.363,8.174
NetD8_1: D8.1 R126.1 TR9.1 | length 7.8
  Top w0.2: TR9.1@56.125,-7.25 56.925,-6.45 58.975,-6.45 60.175,-5.25 D8.1@61.975,-5.25
  Top w0.4: D8.1@61.975,-5.25 R126.1@61.975,-4.1
NetD9_1: D9.1 P1.1
NetF1_1: F1.1 J5.1 | length 2.4
  Bottom w1.524: J5.1@6.95,-6.15 F1.1@6.95,-3.725
NetJ2_17: J2.17 R146.2 | length 2.9
  Bottom w0.203: J2.17@4.976,18.872 5.86,18.872 6.602,18.131 7.262,18.131 R146.2@7.437,17.956 ; R146.2@7.432,17.961 R146.2@7.488,17.961
NetJ2_18: J2.18 R147.2 | length 3
  Top w0.203: v1(-0.625,18.875) R147.2@0.625,18.875
  Bottom w0.203: v1(-0.625,18.875) J2.18@1.076,18.872
NetJ2_25: J2.25 P38.1
NetJ2_26: J2.26 P39.1
NetJ2_27: J2.27 R140.2 | length 2.5
  Bottom w0.203: J2.27@4.976,12.522 R140.2@7.513,12.522
NetJ2_28: J2.28 R141.2 | length 3
  Top w0.203: v1(-0.65,12.525) R141.2@0.6,12.525
  Bottom w0.203: v1(-0.65,12.525) J2.28@1.071,12.517
NetJ3_7: J3.7 P34.1 | length 1.4
  Top w0.203: J3.7@16.325,24.579 P34.1@16.325,26.025
NetJ4_4: J4.4 P37.1
NetJ4_9: J4.9 P35.1
NetJ4_10: J4.10 P36.1
NetJ6_1: J6.1 R97.2 | length 3.9
  Top w0.259: R97.2@73.688,30.662 73.96,30.662 cw(c73.96,29.329) 74.245,30.631 cw(c73.96,29.329) 74.902,30.272 ccw(c76.006,31.376) 76.006,29.815 J6.1@77.341,29.815
NetL6_2: L6.2 R114.1 TR6.1 | length 3.2
  Top w0.4: L6.2@74.525,12 74.525,13.35 ; R114.1@74.525,14.025 74.525,13.35 ; TR6.1@75.725,13.35 74.525,13.35
NetL15_2: L15.2 U2.1 | length 2.4
  Bottom w0.3: U2.1@57.389,-0.403 U2.1@57.389,-0.303
  Bottom w0.5: L15.2@55.514,-0.828 57.389,-0.828 U2.1@57.389,-0.403
NetP2_1: P2.1 U10.1
NetP3_1: P3.1 U10.98
NetP4_1: P4.1 U10.5
NetP5_1: P5.1 U10.38
NetP6_1: P6.1 U10.46
NetP7_1: P7.1 U10.58
NetP8_1: P8.1 U10.88
NetP9_1: P9.1 U10.81
NetP10_1: P10.1 U10.82
NetP11_1: P11.1 U10.83
NetP12_1: P12.1 U10.84
NetP13_1: P13.1 U10.85
NetP14_1: P14.1 U10.86
NetP15_1: P15.1 U10.87
NetP16_1: P16.1 U10.65
NetP17_1: P17.1 U10.66
NetP18_1: P18.1 U10.78
NetP19_1: P19.1 U10.79
NetP20_1: P20.1 U10.80
NetP21_1: P21.1 U10.17
NetP22_1: P22.1 U10.18
NetP23_1: P23.1 U10.23
NetP24_1: P24.1 U10.26
NetP25_1: P25.1 U10.35
NetP26_1: P26.1 U10.92
NetP27_1: P27.1 U10.93
NetP28_1: P28.1 U10.95
NetP29_1: P29.1 U10.96
NetP30_1: P30.1 U10.47
NetP31_1: P31.1 U10.53
NetP32_1: P32.1 U10.54
NetP33_1: P33.1 U10.13
NetP40_1: P40.1 U1.29 | length 0.3
  Top w0.2: U1.29@44.55,13.3 P40.1@44.825,13.3
NetP41_1: P41.1 U19.4
NetP42_1: P42.1 U5.4
NetP43_1: P43.1 U5.5
NetP44_1: P44.1 U5.6
NetP45_1: P45.1 U5.7
NetP46_1: P46.1 U5.36
NetP47_1: P47.1 U5.8
NetP48_1: P48.1 U5.14
NetP49_1: P49.1 U5.26
NetP50_1: P50.1 U5.16
NetP51_1: P51.1 U5.24
NetP52_1: P52.1 U5.28
NetP53_1: P53.1 U5.29
NetP54_1: P54.1 U5.30
NetP55_1: P55.1 U3.20 | length 0.4
  Top w0.2: U3.20@69.675,25.588 70.013,25.588 P55.1@70.025,25.6
NetP56_1: P56.1 U3.10
NetP57_1: P57.1 U3.19 | length 0.4
  Top w0.2: U3.19@69.675,25.088 70.013,25.088 P57.1@70.025,25.1
NetP58_1: P58.1 U6.11 | length 0.3
  Top w0.2: P58.1@36.65,31.525 36.653,31.528 U6.11@36.967,31.528
NetP59_1: P59.1 U6.13 | length 0.3
  Top w0.2: P59.1@36.675,30.525 36.678,30.528 U6.13@36.967,30.528
NetP60_1: P60.1 U6.14 | length 0.3
  Top w0.2: P60.1@36.675,30.025 36.678,30.028 U6.14@36.967,30.028
NetP61_1: P61.1 U6.15 | length 0.3
  Top w0.2: P61.1@36.675,29.525 36.678,29.528 U6.15@36.967,29.528
NetP62_1: P62.1 U6.16 | length 0.3
  Top w0.2: P62.1@36.7,29.025 36.964,29.025 U6.16@36.967,29.028
NetP63_1: P63.1 U6.23 | length 0.3
  Top w0.2: U6.23@40.767,28.228 40.767,27.958 P63.1@40.775,27.95
NetP64_1: P64.1 U6.24 | length 0.3
  Top w0.2: U6.24@41.267,28.228 41.267,27.958 P64.1@41.275,27.95
NetP65_1: P65.1 U6.25 | length 0.3
  Top w0.2: U6.25@41.767,28.228 41.767,27.958 P65.1@41.775,27.95
NetP66_1: P66.1 U6.26 | length 0.3
  Top w0.2: U6.26@42.267,28.228 42.267,27.958 P66.1@42.275,27.95
NetP67_1: P67.1 U6.42 | length 0.3
  Top w0.2: U6.42@46.067,33.528 46.347,33.528 P67.1@46.35,33.525
NetP68_1: P68.1 U6.41 | length 0.3
  Top w0.2: U6.41@46.067,33.028 46.347,33.028 P68.1@46.35,33.025
NetP69_1: P69.1 U8.1
NetP70_1: P70.1 U6.49 | length 0.3
  Top w0.2: U6.49@45.267,37.328 45.275,37.336 P70.1@45.275,37.625
NetP71_1: P71.1 U6.46 | length 0.3
  Top w0.2: U6.46@46.067,35.528 46.372,35.528 P71.1@46.375,35.525
NetP72_1: P72.1 U17.1
NetP89_1: P89.1 U2.13 | length 0.4
  Bottom w0.2: P89.1@59.639,-1.453 U2.13@59.639,-1.053
NetP91_1: P91.1 U2.7 | length 0.4
  Bottom w0.2: U2.7@59.139,1.947 P91.1@59.139,2.347
NetR10_1: R10.1 R11.2 R12.1 U8.4 | length 9.1
  Bottom w0.2: R10.1@53.93,39.797 55.075,39.797 55.888,40.61 59.063,40.61 59.223,40.449 R11.2@59.223,39.822 R12.1@60.942,39.822 U8.4@60.946,38.747
NetR10_2: R10.2 U7.2 | length 2.8
  Bottom w0.203: U7.2@50.839,38.802 50.839,39.58 51.042,39.783 R10.2@52.816,39.783
NetR16_2: R16.2 U10.12 | length 4.1
  Bottom w0.203: U10.12@17.129,28.558 17.129,29.899 18.182,30.952 18.182,32.147 R16.2@18.13,32.147
NetR20_2: R20.2 U10.94 | length 2.8
  Bottom w0.3: R20.2@7.44,23.726 7.722,24.008 U10.94@10.079,24.008
NetR21_1: R21.1 TR3.6 | length 1.2
  Top w0.203: v1(5.329,34.517) R21.1@5.329,35.152
  Bottom w0.203: TR3.6@5.329,33.998 v1(5.329,34.517)
NetR22_1: R22.1 TR3.3 | length 2.1
  Top w0.203: R22.1@7.618,31.745 v1(8.288,31.745)
  Bottom w0.203: TR3.3@7.216,32.685 7.374,32.685 8.288,31.77 v1(8.288,31.745)
NetR24_1: R24.1 U11.6 | length 1.5
  Top w0.381: U11.6@11.304,33.49 11.304,32.213 R24.1@11.48,32.037
NetR25_1: R25.1 R29.2 U11.4 | length 2.4
  Top w0.203: R29.2@9.345,32.038 R25.1@10.353,32.038
  Top w0.381: R29.2@9.404,32.057 U11.4@9.404,33.49
NetR26_1: R26.1 TR5.3 | length 4
  Top w0.203: TR5.3@4.778,31.496 TR5.3@4.976,31.496 5.657,31.496 v1(5.763,31.389)
  Bottom w0.203: R26.1@3.909,32.659 3.909,31.643 4.163,31.389 v1(5.763,31.389)
NetR27_1: R27.1 TR5.6 | length 1.9
  Top w0.203: R27.1@1.225,30.2 TR5.6@3.076,30.196
NetR28_2: R28.2 R29.1 | length 25.7
  Top w0.203: R29.1@9.337,30.946 9.35,30.933 v1(9.35,30.05)
  L2C w0.203: v1(9.35,30.05) 9.35,29.475 9.925,28.9 9.925,19.264 10.939,18.25 10.939,11.347 11.625,10.661 11.65,10.661 12.336,9.975 v1(14.546,9.975)
  Bottom w0.203: v1(14.546,9.975) 14.884,9.637 R28.2@15.638,9.637
NetR30_2: R30.2 R31.2 | length 6.1
  Top w0.5: R31.2@47.732,13.178 49.705,13.178 50.772,14.244 R30.2@53.391,14.244
NetR31_1: R31.1 R36.1 U1.25 | length 3.6
  Top w0.2: U1.25@44.452,11.307 44.552,11.307 45.888,11.307 46.632,12.051 R36.1@46.632,12.162 R31.1@46.632,13.178
NetR35_2: R35.2 T1.1 | length 4.5
  Top w0.5: R35.2@47.732,11.146 50.036,11.146 51.03,10.152 T1.1@51.796,10.152
NetR36_2: R36.2 T1.3 | length 4.3
  Top w0.5: R36.2@47.732,12.162 50.196,12.162 50.736,12.702 T1.3@51.796,12.702
NetR40_2: R40.2 R41.2 U1.61 | length 5.4
  Top w0.2: R41.2@31.324,9.048 31.566,8.807 U1.61@35.552,8.807
  Top w0.203: R41.2@31.324,9.048 R40.2@31.324,10.073
NetR42_2: R42.2 R43.2 U1.62 | length 4.3
  Top w0.2: R43.2@32.274,8.073 32.508,8.307 U1.62@35.552,8.307
  Top w0.203: R42.2@31.324,8.048 R43.2@32.249,8.048
NetR43_1: R43.1 R44.2 U1.63 | length 4.7
  Top w0.2: R44.2@31.773,6.073 31.773,6.472 R43.1@32.274,6.973 33.108,7.807 U1.63@35.552,7.807
NetR46_1: R46.1 U1.58 | length 2
  Top w0.2: v1(34.688,10.312) U1.58@35.388,10.312
  Bottom w0.2: R46.1@33.381,10.304 33.389,10.312 v1(34.688,10.312)
NetR68_2: R68.2 R71.2 U1.18 | length 5.3
  Top w0.2: U1.18@44.552,7.807 45.322,7.807 45.891,7.239 45.891,6.909 46.577,6.222 46.577,5.604 R71.2@47.191,4.991 R68.2@47.191,4.041
NetR69_2: R69.2 U1.37 | length 2.3
  Top w0.2: U1.37@41.752,15.507 41.752,17.007 R69.2@42.297,17.552
NetR70_2: R70.2 U1.44 | length 2.3
  Top w0.2: R70.2@37.705,17.55 38.252,17.003 U1.44@38.252,15.507
NetR71_1: R71.1 R72.2 U1.19 | length 3.9
  Top w0.2: U1.19@44.452,8.307 44.552,8.307 45.399,8.307 R72.2@46.624,7.082 47.191,6.515 R71.1@47.191,6.091
NetR73_2: R73.2 R74.2 U1.20 | length 2.9
  Top w0.2: U1.20@44.452,8.807 44.552,8.807 46.601,8.807 ; R73.2@46.624,8.098 46.624,8.807
NetR87_2: R87.2 U5.10 | length 3.4
  Top w0.2: R87.2@63.412,32.688 66.237,32.688 66.372,32.823 U5.10@66.372,33.235
NetR94_1: R94.1 R95.1 R96.2 R97.1 | length 2.9
  Top w0.259: R95.1@71.632,29.658 R94.1@72.567,29.658 ; R95.1@71.638,29.665 R96.2@71.638,30.688 R97.1@72.562,30.688
NetR98_2: R98.2 R100.1 U5.19 | length 3
  Top w0.203: U5.19@71.372,34.185 72.04,34.185 72.225,34 v1(72.225,33.675)
  Bottom w0.4: R100.1@71.4,33.725 v1(72.225,33.675) R98.2@73.125,33.675
NetR99_1: R99.1 U5.18 | length 1.6
  Top w0.2: U5.18@70.372,33.235 70.372,31.858 R99.1@70.54,31.69
NetR105_1: R105.1 U3.31 | length 1.4
  Top w0.203: v1(62.986,25.58) U3.31@63.686,25.58
  Bottom w0.203: v1(62.986,25.58) 63.374,25.192 R105.1@63.548,25.192
NetR107_1: R107.1 TP15.1 U3.38 | length 6.2
  Top w0.203: v1(62.986,22.08) U3.38@63.686,22.08
  Bottom w0.203: R107.1@59.444,19.695 TP15.1@59.444,21.358 61.076,21.358 61.798,22.08 v1(62.986,22.08)
NetR108_1: R108.1 TP16.1 U3.39 | length 6.8
  Top w0.203: v1(62.586,21.58) U3.39@63.686,21.58
  Bottom w0.203: R108.1@59.5,18.718 62.362,21.58 v1(62.586,21.58) ; TP16.1@59.517,17.156 R108.1@59.517,18.581
NetR109_1: R109.1 TP18.1 U3.36 | length 6.6
  Top w0.203: v1(62.986,23.08) U3.36@63.686,23.08
  Bottom w0.203: TP18.1@59.5,27.138 R109.1@59.5,25.925 62.345,23.08 v1(62.986,23.08)
NetR110_1: R110.1 TP19.1 U3.37 | length 6.1
  Top w0.203: v1(62.586,22.58) U3.37@63.686,22.58
  Bottom w0.203: R110.1@59.44,24.815 TP19.1@59.44,23.303 61.072,23.303 61.795,22.58 v1(62.586,22.58)
NetR115_1: R115.1 U3.28 | length 2.1
  Top w0.203: U3.28@65.556,26.421 v1(65.556,27.521)
  Bottom w0.203: v1(65.556,27.521) 66.063,28.029 R115.1@66.063,28.265
NetR119_1: R119.1 R120.2 U3.12 | length 3.3
  Top w0.203: U3.12@69.75,21.575 71.325,21.575 71.575,21.825 R120.2@71.575,22.225
  Top w0.254: R120.2@71.575,22.225 R119.1@71.575,23.225
NetR124_2: R124.2 TR7.1 | length 1.2
  Top w0.381: R124.2@65.375,-5.15 TR7.1@65.375,-4
NetR125_2: R125.2 TR8.1 | length 1.2
  Top w0.4: R125.2@69.65,-0.9 TR8.1@70.825,-0.9
NetR126_2: R126.2 TR7.3 | length 1.2
  Top w0.4: R126.2@61.975,-3 TR7.3@63.175,-3
NetR127_2: R127.2 R128.1 | length 1
  Top w0.4: R127.2@69.65,0.1 R128.1@69.65,1.1
NetR142_1: R142.1 R144.1 U12.3 | length 39.4
  Top w0.203: R144.1@20.111,32.126 v1(22.629,32.126)
  Top w0.5: R142.1@16.983,3.057 U12.3@18.4,3.057
  L2C w0.203: v1(17.618,3.082) 17.092,3.608 17.092,5.909 19.849,8.666 23.113,8.666 25.039,10.592 25.039,24.27 24.712,24.598 24.712,30.069 22.654,32.126 v1(22.629,32.126)
NetT3_1: T3.1 U1.8 | length 7.2
  Top w0.2: T3.1@38.69,-0.135 38.69,0.993 39.393,1.697 39.393,5.1 39.752,5.459 U1.8@39.752,6.607
NetT3_3: T3.3 U1.9 | length 7.2
  Top w0.2: U1.9@40.249,6.642 40.249,5.494 40.607,5.135 40.607,1.732 41.24,1.1 T3.3@41.24,-0.135
NetTP24_1: TP24.1 U6.51 | length 2.5
  Top w0.2: U6.51@44.267,37.228 U6.51@44.267,37.328 44.267,38.698 TP24.1@44.999,39.429
NetTP25_1: TP25.1 U6.52 | length 2.4
  Top w0.2: TP25.1@43.297,39.429 43.767,38.959 U6.52@43.767,37.328 U6.52@43.767,37.228
NetU3_14: U3.14 U3.15 | length 0.5
  Top w0.203: U3.14@69.75,22.575 U3.15@69.75,23.075
NetU3_16: U3.16 U3.17 | length 0.5
  Top w0.203: U3.16@69.75,23.575 U3.17@69.75,24.075
NRST: C25.2 J3.10 R17.2 U10.14 | length 15
  Top w0.203: v1(13.936,22.091) 14.673,22.091 14.789,21.975 J3.10@14.789,21.304 ; C25.2@18.129,29.197 v1(18.129,30.021) 18.129,30.206 R17.2@18.986,31.062
  L5C w0.203: v1(13.936,22.091) 16.9,25.055 16.9,28.792 v1(18.129,30.021)
  Bottom w0.203: U10.14@18.129,28.508 U10.14@18.129,28.558 v1(18.129,30.021)
NSTANDBY: R144.2 U10.7 | length 8.2
  Top w0.203: v1(14.629,30.422) 14.629,31.729 15.675,32.775 17.575,32.775 18.246,32.104 R144.2@18.986,32.104
  Bottom w0.203: U10.7@14.629,28.558 v1(14.629,30.422)
PA_FEEDBACK: C157.2 T2.6 | length 37.9
  Top w0.304: T2.6@41.23,23.442 41.078,23.442 T2.6@41.373,23.147 ; C157.2@71.3,7.75 v4(71.3,8.65)
  Top w0.305: T2.6@41.373,23.147 v9(42.186,23.147)
  L3C w0.34: v9(42.186,23.147) 42.186,22.374 44.143,20.417 46.353,20.417 49.121,17.648 55.751,17.648 62.818,10.58 69.37,10.58 v4(71.3,8.65)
